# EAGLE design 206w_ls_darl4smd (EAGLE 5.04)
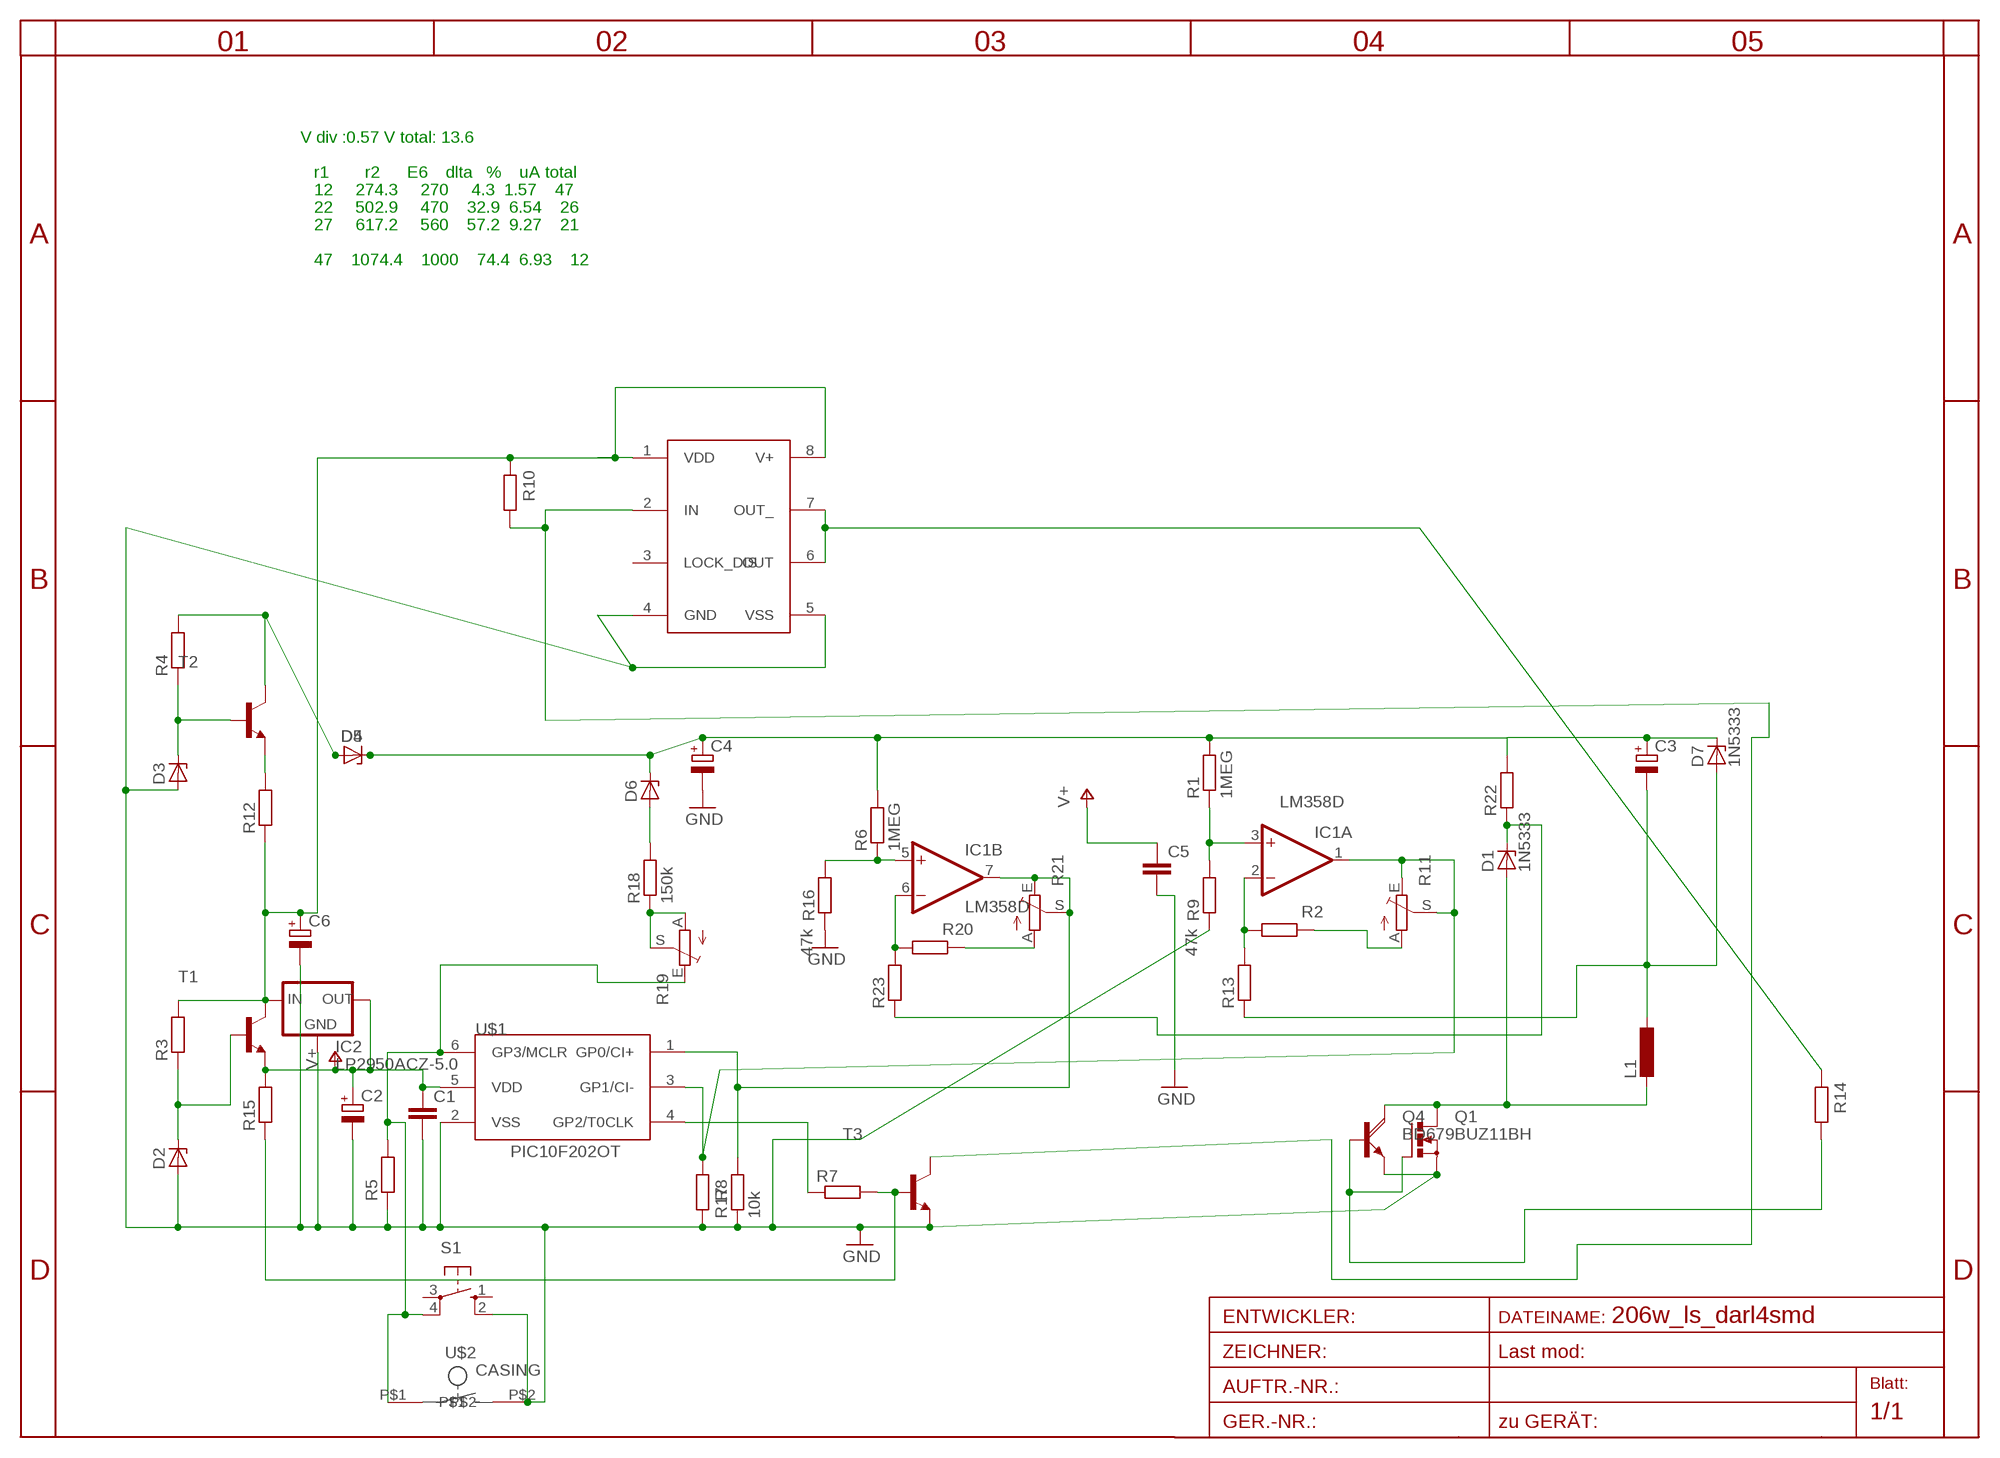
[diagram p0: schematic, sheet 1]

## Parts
C1  C-EUC1206  [C1206]
C2  CPOL-EUSANYO_SMD_E12  [SANYO-OSCON_SMD_E12]
C3  CPOL-EUE5-8.5  [E5-8,5]
C4  CPOL-EUE5-8.5  [E5-8,5]
C5  C-EUC1206  [C1206]
C6  CPOL-EUSANYO_SMD_E12  [SANYO-OSCON_SMD_E12]
D1  1N5333  [C1702-15]
D2  ZENER-DIODESOT23  [SOT23]
D3  ZENER-DIODESMB  [SMB]
D4  ZENER-DIODESMB  [SMB]
D5  ZENER-DIODESMB  [SMB]
D6  ZENER-DIODESMB  [SMB]
D7  1N5333  [C1702-15]
IC1  LM358D  [SO08]
IC2  LP2950ACZ-5.0  [TO92]
IC3  TC4432X  [SO-08]
L1  L-EU2200-15.24  [2200-15.24]
Q1  BUZ11BH  [TO220BH]
Q4  BD679  [TO126AV]
R1  1MEG  R-EU_R1206  [R1206]
R2  R-EU_R0805  [R0805]
R3  R-EU_R0805  [R0805]
R4  R-EU_R0805  [R0805]
R5  R-EU_R0805  [R0805]
R6  1MEG  R-EU_R1206  [R1206]
R7  R-EU_R0805  [R0805]
R8  R-EU_R0805  [R0805]
R9  47k  R-EU_R0805  [R0805]
R10  R-EU_R0805  [R0805]
R11  TRIM_EU-CA6V  [CA6V]
R12  R-EU_R0805  [R0805]
R13  R-EU_R1206  [R1206]
R14  R-EU_0207/10  [0207/10]
R15  R-EU_R0805  [R0805]
R16  47k  R-EU_R0805  [R0805]
R17  10k  R-EU_R0805  [R0805]
R18  150k  R-EU_R1206  [R1206]
R19  TRIM_EU-CA6V  [CA6V]
R20  R-EU_R0805  [R0805]
R21  TRIM_EU-CA6V  [CA6V]
R22  R-EU_0309/12  [0309/12]
R23  R-EU_R1206  [R1206]
S1  10-XX  [B3F-10XX]
T1  BC846BLT1-NPN-SOT23-BEC  [SOT23-BEC]
T2  BC846BLT1-NPN-SOT23-BEC  [SOT23-BEC]
T3  BC846BLT1-NPN-SOT23-BEC  [SOT23-BEC]
U$1  PIC10F202OT  [SOT23-6]
U$2  CASING  [CASING]

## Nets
BB: IC3.2(IN) R10.1 T3.C
GND: C1.2 C2.- C4.- C5.2 C6.- D2.1(A) D3.A IC2.2(GND) IC3.4(GND) IC3.5(VSS) Q1.S Q4.E R5.1 R8.1 R9.1 R16.1 R17.1 S1.2(S1) T3.E U$1.2(VSS) U$2.P$2
HOTSPOT: D1.A L1.2 Q1.D Q4.C
N$1: IC1.1(A:OUT) R8.2 R11.E R11.S U$1.3(GP1/CI-)
N$2: R2.1 R11.A
N$3: Q1.G Q4.B R14.1
N$5: IC1.5(B:+IN) R6.1 R16.2
N$6: D2.3(C) R3.1 T1.B
N$7: R5.2 R19.E S1.4(P1) U$1.6(GP3/MCLR) U$2.P$1
N$8: IC1.3(A:+IN) R1.1 R9.2
N$9: R7.1 U$1.4(GP2/T0CLK)
N$11: IC3.6(OUT) IC3.7(OUT_) R14.2
N$12: D3.C R4.1 T2.B
N$13: R18.1 R19.A R19.S
N$14: IC1.7(B:OUT) R17.2 R21.E R21.S U$1.1(GP0/CI+)
N$15: IC1.2(A:-IN) R2.2 R13.2
N$17: R7.2 R15.1 T3.B
N$21: D4.A D5.A R4.2 T2.C
N$22: R12.2 T2.E
N$23: D6.A R18.2
N$24: IC1.6(B:-IN) R20.2 R23.2
N$25: R20.1 R21.A
N$26: D1.C R22.1 R23.1
V60: C3.+ C4.+ D4.C D5.C D6.C D7.C R1.2 R6.2 R22.2
V+: C1.1 C2.+ C5.1 IC2.1(OUT) R15.2 T1.E U$1.5(VDD)
VCC: C6.+ IC2.3(IN) IC3.1(VDD) IC3.8(V+) R3.2 R10.2 R12.1 T1.C
VOUT: C3.- D7.A L1.1 R13.1
Unconnected: IC3.3(LOCK_DIS) S1.1(S) S1.3(P)

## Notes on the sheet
- V div :0.57 V total: 13.6
- r1        r2      E6    dlta   %    uA total
- 12     274.3     270     4.3  1.57    47
- 22     502.9     470    32.9  6.54    26
- 27     617.2     560    57.2  9.27    21
- 47    1074.4    1000    74.4  6.93    12

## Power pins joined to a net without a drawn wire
GND: IC1.4(P:V-)
V+: IC1.8(P:V+)

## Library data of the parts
C1 C5 = rcl:C-EU: CAPACITOR, European symbol
C2-C4 C6 = rcl:CPOL-EU: POLARIZED CAPACITOR, European symbol
D1 D7 = diode-1:1N5333: Z DIODE
D2-D6 = diode-1:ZENER-DIODE: Z-Diode
IC1 = linear4:LM358: OP AMP
IC2 = v-reg:LP2950?*: Source: http://cache.national.com/ds/LP/LP2950.pdf
IC3 = microchip:TC4432
L1 = rcl:L-EU: INDUCTOR, European symbol
Q1 = transistor-power:BUZ11: N-CHANNEL MOS FET
Q4 = transistor-power:BD679: NPN DARLINGTON TRANSISTOR
R1-R6 R8-R10 R12 R14-R16 R20 = rcl:R-EU_: RESISTOR, European symbol
R7 R13 R17 R18 R22 R23 = rcl-2:R-EU_: RESISTOR, European symbol
R11 R19 R21 = pot:TRIM_EU-: POTENTIOMETER
S1 = switch-omron:10-XX: OMRON SWITCH
T1-T3 = transistor-neu-to92:*-NPN-: NPN Transistror
U$1 = microchip-5:PIC10F2*: uPC nW 0,25/0,5k Program Flash memory Comparator
U$2 = button:CASING

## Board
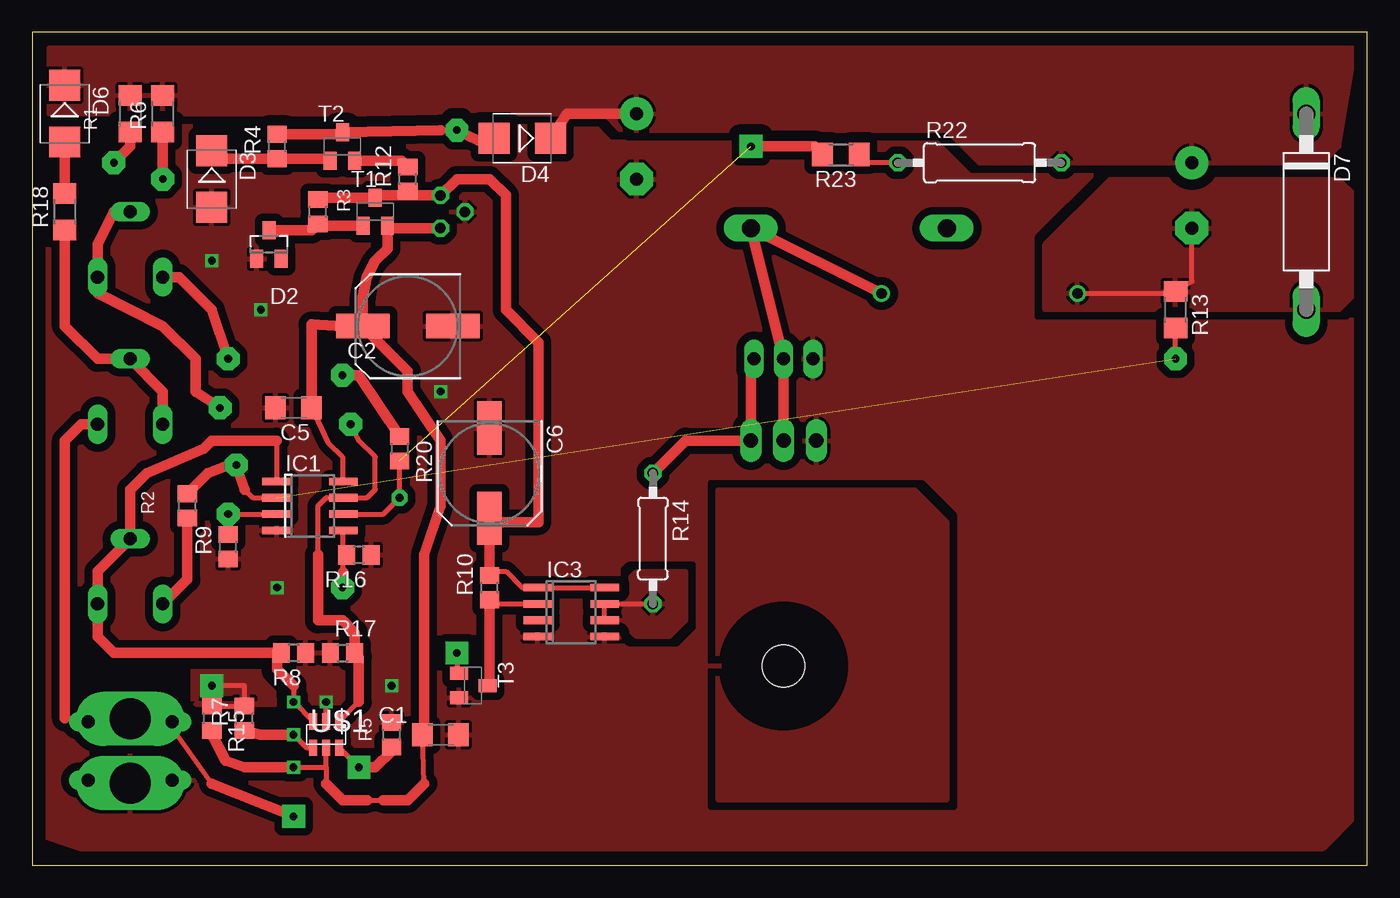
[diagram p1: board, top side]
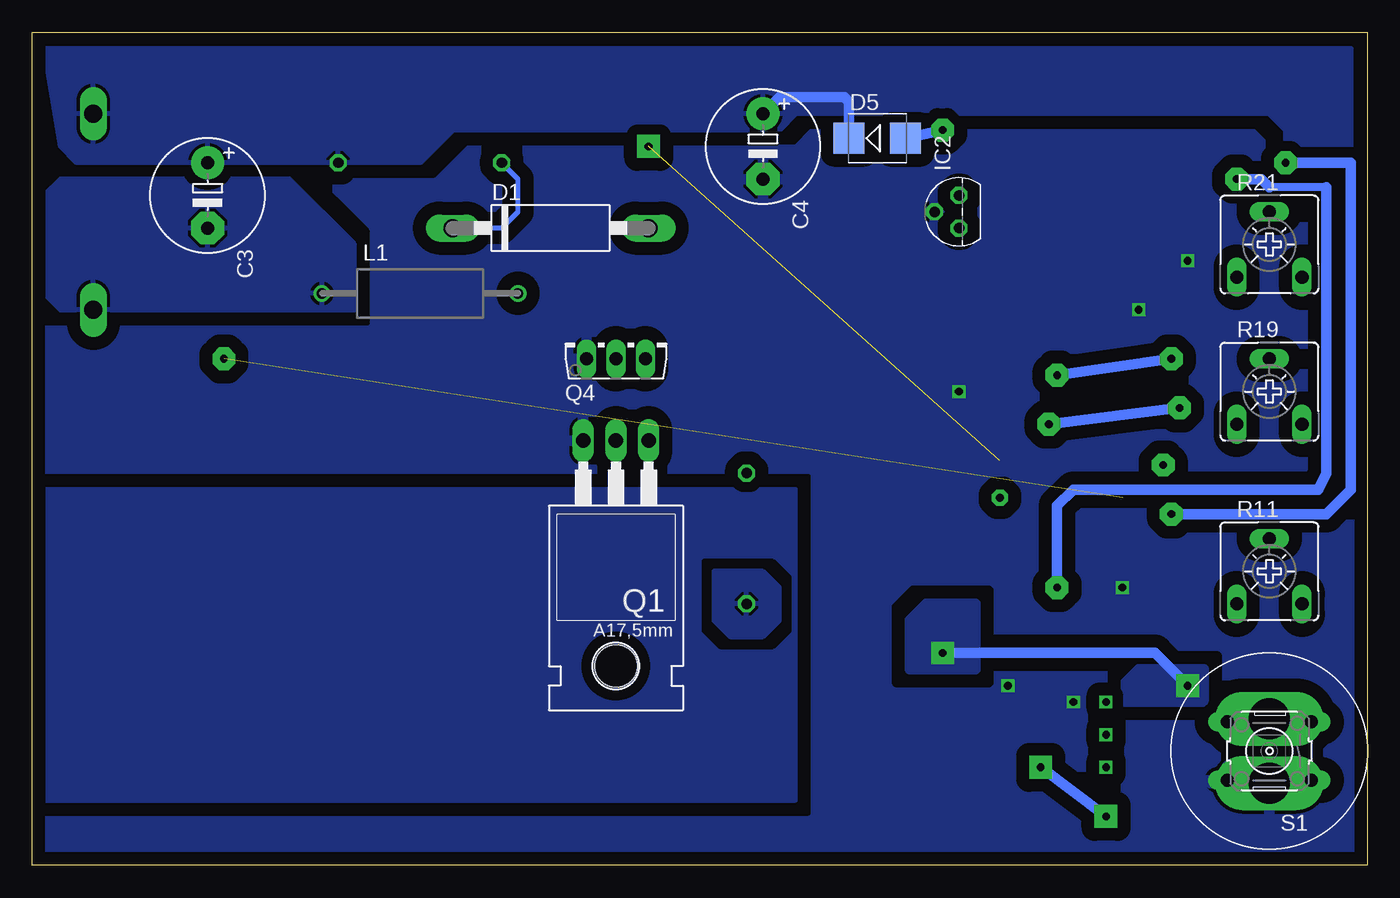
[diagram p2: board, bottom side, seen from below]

Size 103.81 x 64.76 mm. Coordinates in mm from the lower left corner, seen from the top.
Outline: 0,0 103.81,0 103.81,64.76 0,64.76 0,0
Copper layers (1*16): Top 0.035mm / dielectric 1.5mm / Bottom 0.035mm
Design rules "default": minimum track width 10mil, minimum drill 24mil, track to track 8mil, track to pad 8mil, pad to pad 8mil, via to via 8mil, smd to smd 8mil, copper to edge 40mil, drill to drill 8mil, minimum pad ring 10mil, minimum via ring 8mil, stop-mask expansion 4mil, vias tented up to drill 0mil, thermal gap 10mil

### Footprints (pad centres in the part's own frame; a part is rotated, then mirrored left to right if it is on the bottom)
C1206 = smd 1.6 x 1.8: 1 -1.4,0; 2 1.4,0
SANYO-OSCON_SMD_E12 = smd 4.15 x 1.9: + 3.5,0; - -3.5,0
E5-8,5 = drill 1.016 pad 2.54 round: + -2.54,0 | drill 1.016 pad 2.54 octagon: - 2.54,0
C1702-15 = drill 1.397 long: A 7.62,0; C -7.62,0
SOT23 = smd 1 x 1.4: 1 -0.95,-1.1; 2 0.95,-1.1; 3 0,1.1
SMB = smd 2.4 x 2.4: A 2.2,0; C -2.2,0
SO08 = smd 0.6 x 2.2: 1 -1.905,-2.6; 2 -0.635,-2.6; 3 0.635,-2.6; 4 1.905,-2.6; 5 1.905,2.6; 6 0.635,2.6; 7 -0.635,2.6; 8 -1.905,2.6
TO92 = drill 0.813 octagon: 1 -1.27,0; 2 0,1.905; 3 1.27,0
SO-08 = smd 0.6 x 2.2: 1 -1.905,-2.6; 2 -0.635,-2.6; 3 0.635,-2.6; 4 1.905,-2.6; 5 1.905,2.6; 6 0.635,2.6; 7 -0.635,2.6; 8 -1.905,2.6
2200-15.24 = drill 0.8 pad 1.27 round: 1 -7.62,0; 2 7.62,0
TO220BH = drill 1.118 long: D 0,-6.35; G -2.54,-6.35; S 2.54,-6.35 | hole 3.302: 0,11.176
TO126AV = drill 1.016 long: B 2.286,-1.27; C 0,-1.27; E -2.286,-1.27
R1206 = smd 1.6 x 1.803: 1 -1.422,0; 2 1.422,0
R0805 = smd 1.3 x 1.5: 1 -0.95,0; 2 0.95,0
CA6V = drill 1.016 long: A -2.54,-2.54; E 2.54,-2.54; S 0,2.54
0207/10 = drill 0.813 octagon: 1 -5.08,0; 2 5.08,0
0309/12 = drill 0.813 octagon: 1 -6.35,0; 2 6.35,0
B3F-10XX = drill 1.016 long: 1 -3.251,2.261; 2 3.251,2.261; 3 -3.251,-2.261; 4 3.251,-2.261
SOT23-BEC = smd 1 x 1.4: B -0.95,-1.1; C 0,1.1; E 0.95,-1.1
SOT23-6 = smd 0.635 x 1.27: 1 -1.016,-1.016; 2 0,-1.016; 3 1.016,-1.016; 4 1.016,1.016; 5 0,1.016; 6 -1.016,1.016
CASING = drill 3.2 pad 3.81 long: P$1 -2.5,0; P$2 2.5,0

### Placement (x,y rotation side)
C1  31.75,10.16 0 top
C2  29.21,41.91 180 top
C3  90.17,52.07 270 bottom
C4  46.99,55.88 270 bottom
C5  20.32,35.56 180 top
C6  35.56,30.48 270 top
D1  63.5,49.53 0 bottom
D2  18.41,48.26 0 top
D3  13.97,53.34 270 top
D4  38.1,56.52 180 top
D5  38.1,56.52 0 bottom
D6  2.54,58.42 270 top
D7  99.06,50.8 270 top
IC1  21.59,27.94 270 top
IC2  31.75,50.8 90 bottom
IC3  41.91,19.68 270 top
L1  73.66,44.45 0 bottom
Q1  58.42,26.67 180 bottom
Q4  58.42,40.64 0 bottom
R1  7.62,58.42 90 top
R2  12.06,27.94 90 top
R3  22.23,50.8 90 top
R4  19.05,55.88 90 top
R5  27.94,10.16 270 top
R6  10.16,58.42 90 top
R7  16.51,11.43 90 top
R8  20.32,16.51 180 top
R9  15.24,24.77 90 top
R10  35.56,21.59 90 top
R11  7.62,22.86 0 bottom
R12  29.21,53.34 90 top
R13  88.9,43.18 270 top
R14  48.26,25.4 270 top
R15  13.97,11.43 270 top
R16  25.4,24.13 180 top
R17  24.13,16.51 0 top
R18  2.54,50.8 90 top
R19  7.62,36.83 0 bottom
R20  28.57,32.38 270 top
R21  7.62,48.26 0 bottom
R22  73.66,54.61 0 top
R23  62.87,55.24 180 top
S1  7.62,8.89 180 bottom
T1  26.67,50.8 0 top
T2  24.13,55.88 0 top
T3  34.29,13.97 270 top
U$1  22.86,10.16 180 top
U$2  7.62,8.89 270 bottom

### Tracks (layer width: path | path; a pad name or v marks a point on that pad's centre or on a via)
BB
  Top 0.406: T3.C 35.56,13.97 | IC3.2 35.88,20.32 R10.1
  Top 0.813: 35.56,13.97 R10.1
GND  (via drill 0.6)
  Top 0.406: U$1.2 v22.86,12.7
  other vias: 17.78,43.18 13.97,46.99 19.05,21.59 31.75,36.83 27.94,13.97
  pour Bottom (isolate 1.016, rank 5): 102.87,60.96 102.87,0 90.17,0 1.27,1.27 1.27,53.34 1.27,58.42
  pour Top (isolate 0.61, rank 5): 1.27,63.5 99.06,63.5 102.87,59.69 102.87,3.81 100.33,1.27 3.81,1.27 0,2.54
HOTSPOT
  Top 0.813: L1.2 D1.A Q4.C Q1.D
N$1
  Top 0.406: 19.05,33.02 18.99,33.02 IC1.1 | U$1.3 20.32,12.7 20.32,13.97 | R8.2 19.05,16.19
  Top 0.813: 18.99,33.02 13.97,33.02 13.34,32.38 8.89,30.48 7.62,29.21 R11.S 5.08,22.86 R11.E 5.08,17.78 6.35,16.51 R8.2 | 20.32,13.97 19.05,15.24 19.05,16.19
N$2
  Top 0.813: R2.1 12.06,22.23 R11.A
N$3
  Top 0.406: 55.88,39.12 Q4.B
  Top 0.813: R14.1 50.8,33.02 Q1.G 55.88,39.12
N$4  (via drill 0.6)
  other vias: 20.32,12.7
N$5  (via drill 0.6 pad 1.78)
  Top 0.406: 24.19,24.39 R16.2 | 24.19,22.8 24.19,24.39 | 24.19,24.39 IC1.5
  Top 0.813: v10.16,53.34 R6.1 | v24.13,21.59 24.19,22.8
  Bottom 0.61: 3.17,52.7 7.62,52.7
  Bottom 0.813: v10.16,53.34 8.26,53.34 7.62,52.7 | 3.17,52.7 3.17,52.07 3.17,30.48 3.81,29.21 22.86,29.21 24.13,27.94 v24.13,21.59
N$6
  Top 0.406: 22.38,49.7 R3.1 21.73,49.36
  Top 0.813: 22.38,49.7 T1.B | D2.3 21.73,49.36
N$7  (via drill 0.6 pad 1.78)
  Top 0.406: 2.54,11.43 7.58,11.43 U$2.P$1 10.79,10.79 | v25.4,7.62 U$1.6 | 10.79,10.79 13.97,6.35 | 10.79,10.79 10.16,10.44 S1.4 | 27.94,8.89 R5.2
  Top 0.813: R19.E 3.81,34.29 2.54,33.02 2.54,11.43 | 13.97,6.35 v20.32,3.81 | v25.4,7.62 26.67,7.62 27.94,8.89
  Bottom 0.813: v20.32,3.81 v25.4,7.62
N$8  (via drill 0.6 pad 1.78)
  Top 0.406: IC1.3 15.56,27.3 R9.2 v15.24,27.3
  Top 0.813: R1.1 7.62,55.88 v6.35,54.61
  Bottom 0.813: v6.35,54.61 1.27,54.61 1.27,29.21 3.17,27.3 v15.24,27.3
N$9
  Top 0.406: U$1.4 21.34,9.14 20.32,10.16
  Top 0.813: R7.1 17.78,10.16 20.32,10.16
N$11
  Top 0.406: R14.2 IC3.7 IC3.6
  pour Bottom (isolate 0.813): 45.72,21.59 46.99,22.86 50.8,22.86 50.8,19.05 49.53,17.78 46.99,17.78 45.72,19.05
  pour Top (isolate 0.813): 45.72,21.59 46.99,22.86 50.8,22.86 50.8,19.05 49.53,17.78 46.99,17.78 45.72,19.05
N$12
  Top 0.406: D3.C 13.97,55.88
  Top 0.813: T2.B 23.03,54.93 R4.1 14.58,54.93 D3.C
N$13
  Top 0.813: R18.1 2.54,41.91 5.08,39.37 R19.S 10.16,36.83 R19.A
N$14  (via drill 0.6 pad 1.78)
  Top 0.406: v24.77,34.29 25.4,33.02 26.67,31.75 26.67,29.21 26.04,28.57 IC1.7 22.86,28.57 22.23,27.94 22.23,24.13 | 5.08,44.45 R21.E | U$1.1 25.4,12.7 | 25.4,16.19 R17.2
  Top 0.813: v14.61,35.56 12.7,36.83 12.7,39.37 10.16,41.91 5.08,44.45 | R21.E 5.08,48.26 6.35,50.8 R21.S | 25.4,12.7 25.4,16.19 | R17.2 25.08,18.1 24.13,19.05 22.23,19.05 22.23,24.13
  Bottom 0.813: v24.77,34.29 v14.61,35.56
N$15  (via drill 0.6 pad 1.78)  (1 unrouted)
  Top 0.406: 16.51,29.21 17.14,28.57 IC1.2 | v88.9,39.37 R13.2 | 15.24,31.11 v15.88,31.11
  Top 0.813: R2.2 13.65,30.48 15.24,31.11 | v15.88,31.11 16.51,29.21
N$16  (via drill 0.6)
  other vias: 20.32,10.16
N$17  (via drill 0.6 pad 1.78)
  Top 0.406: R15.1 R7.2 16.51,13.97 v13.97,13.97 | v33.02,16.51 33.02,15.09 T3.B
  Bottom 0.813: v13.97,13.97 16.51,16.51 v33.02,16.51
  pour Top (isolate 0.813, rank 3): 12.7,15.24 17.78,15.24 20.32,12.7 12.7,12.7
  pour Bottom (isolate 0.813, rank 3): 30.48,20.32 34.29,20.32 35.56,19.05 35.56,15.24 30.48,15.24
  pour Bottom (isolate 0.813, rank 3): 12.7,15.24 17.78,15.24 20.32,12.7 12.7,12.7
N$18  (via drill 0.6)
  other vias: 20.32,7.62
N$20
  pour Top (isolate 0.813, rank 3): 53.34,29.21 68.58,29.21 71.12,26.67 71.12,5.08 53.34,5.08
  pour Bottom (isolate 0.813, rank 3): 44.45,29.21 102.87,29.21 102.87,5.08 44.45,5.08
N$21  (via drill 0.6 pad 1.78)
  Top 0.406: 35.56,55.88 D5.A | 31.75,57.15 v33.02,57.15
  Top 0.813: R4.2 23.98,56.83 T2.C 31.75,57.15 | v33.02,57.15 35.56,55.88
  Bottom 0.813: v33.02,57.15 D5.A
N$22
  Top 0.813: T2.E 28.72,54.78 R12.2
N$23
  Top 0.813: R18.2 D6.A
N$24  (via drill 0.6 pad 1.27, 0.6 pad 1.78)  (1 unrouted)
  Top 0.406: 60.81,55.88 R23.2 | IC1.6 27.3,27.3 v28.57,28.57 R20.2
  Top 0.813: v55.88,55.88 60.81,55.88
N$25  (via drill 0.6 pad 1.78)
  Top 0.813: R21.A 11.43,45.72 13.97,43.18 v15.24,39.37 | v24.13,38.1 25.4,38.1 R20.1
  Bottom 0.813: v15.24,39.37 v24.13,38.1
N$26
  Top 0.406: R22.1 64.92,54.61 R23.1
  Bottom 0.406: D1.C 67.31,49.53 66.04,50.8 66.04,53.34 R22.1
V60
  Top 0.813: C4.+ 41.57,58.42 D5.C
  Bottom 0.813: D5.C 40.3,59.35 40.64,59.69 45.72,59.69 C4.+
  pour Top (isolate 0.813, rank 4): 102.87,63.5 1.27,63.5 1.27,58.42 44.45,58.42 45.72,57.15 71.12,57.15 73.66,54.61 100.33,54.61 101.6,55.88
  pour Bottom (isolate 0.813, rank 4): 102.87,63.5 1.27,63.5 1.27,48.26 7.62,48.26 7.62,54.61 6.35,55.88 6.35,57.15 7.62,58.42 44.45,58.42 45.72,57.15 71.12,57.15 73.66,54.61 100.33,54.61 101.6,55.88
V+
  Top 0.406: 15.04,8.13 13.69,10.16 | 30.48,6.35 C1.1 30.48,10.16 | 22.86,7.62 22.86,6.35 | 22.86,7.62 U$1.5 | 13.97,10.24 R15.2 | T1.E 27.79,49.53 | 20.32,7.62 22.86,7.62 | 26.04,5.08 27.3,5.08 | C2.+ 24.13,41.91 | C5.1 22.99,32.89 24.13,31.75 24.13,29.91 IC1.8
  Top 0.813: 30.48,6.35 29.21,5.08 27.3,5.08 | 22.86,6.35 24.13,5.08 26.04,5.08 | 13.97,10.24 15.04,8.13 16.51,7.62 20.32,7.62 | 27.79,49.53 IC2.1 | T1.E 27.62,47.94 26.67,46.99 26.02,45.72 25.71,44.14 C2.+ 29.21,38.41 29.21,36.83 31.75,33.02 31.75,27.94 30.48,24.13 30.48,10.16 | C5.1 21.72,42.04 24.13,41.91
VCC
  Top 0.406: IC3.8 IC3.1 38.1,21.59 36.83,22.86 35.88,22.86 R10.2 | 35.56,26.67 C6.+ | 26.84,52.07 T1.C | 22.38,51.9 R3.2
  Top 0.813: R10.2 35.56,26.67 39.37,26.67 39.37,40.64 36.83,43.18 36.83,52.07 35.56,53.34 33.02,53.34 IC2.3 29.21,52.07 | T1.C 22.38,51.9 | 29.21,52.07 26.84,52.07 | 29.21,52.07 R12.1
VOUT
  Top 0.406: L1.1 88.58,44.45 R13.1 90.17,45.4 C3.-
  pour Top (isolate 0.813, rank 3): 101.6,53.34 102.87,52.07 102.87,44.45 101.6,43.18 78.74,43.18 78.74,48.26 83.82,53.34
  pour Bottom (isolate 0.813, rank 3): 101.6,53.34 102.87,52.07 102.87,44.45 101.6,43.18 78.74,43.18 78.74,48.26 83.82,53.34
